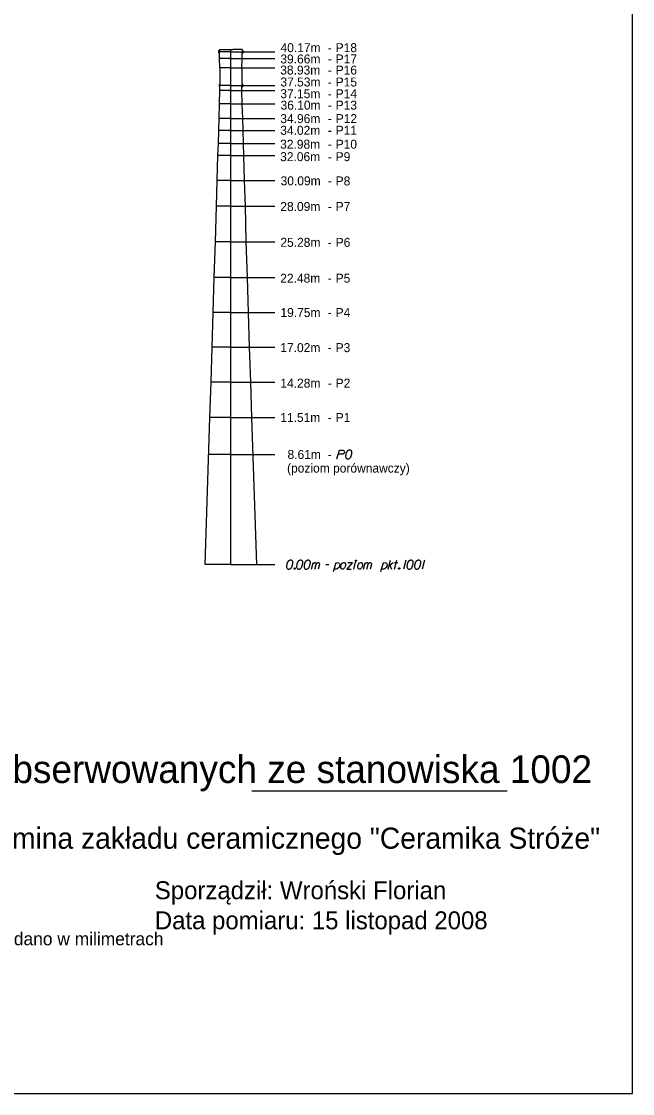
# Model space of a CAD drawing. Extents: x 138 to 6653, y -177 to 1520.
# Drawn here: x 387.51 to 398.01, y 2.29 to 20.71 of the extents above; entities that cross this region are included whole.
import ezdxf

# ---------------------------------------------------------------- set-up
doc = ezdxf.new("R2010")
doc.units = 0
doc.layers.add('Opisy', color=7, linetype='Continuous')
doc.layers.add('Ramka do drukowania', color=7, linetype='Continuous')

msp = doc.modelspace()

# ---------------------------------------------------------------- linework, layer by layer
at = {"layer": 'Opisy'}
for p, q in [((390.893, 20.204), (390.893, 20.185)), ((390.91, 20.204), (390.893, 20.204)), ((391.106, 20.185), (390.893, 20.185)), ((390.893, 20.185), (390.893, 20.166)), ((390.91, 20.166), (390.893, 20.166)), ((390.91, 20.222), (390.91, 20.204)), ((390.91, 20.222), (391.137, 20.222)), ((390.91, 20.072), (390.91, 20.166)), ((391.106, 11.376), (391.106, 20.222)), ((391.106, 20.185), (391.859, 20.185)), ((391.302, 20.222), (391.137, 20.222)), ((391.302, 20.222), (391.302, 20.204)), ((391.302, 20.204), (391.319, 20.204)), ((391.302, 20.166), (391.319, 20.166)), ((391.302, 20.072), (391.302, 20.166)), ((391.319, 20.204), (391.319, 20.185)), ((391.319, 20.185), (391.319, 20.166)), ((391.106, 20.072), (390.91, 20.072)), ((390.916, 19.912), (390.91, 20.072)), ((391.106, 19.912), (390.916, 19.912)), ((390.916, 19.912), (390.916, 19.624)), ((391.106, 20.072), (391.859, 20.072)), ((391.106, 19.912), (391.859, 19.912)), ((391.296, 19.912), (391.302, 20.072)), ((391.296, 19.912), (391.296, 19.624)), ((390.903, 19.624), (390.903, 19.605)), ((390.903, 19.624), (390.916, 19.624)), ((391.106, 19.605), (390.903, 19.605)), ((390.903, 19.605), (390.903, 19.586)), ((390.918, 19.586), (390.903, 19.586)), ((390.916, 19.522), (390.918, 19.586)), ((391.106, 19.605), (391.859, 19.605)), ((391.296, 19.522), (391.294, 19.586)), ((391.294, 19.586), (391.309, 19.586)), ((391.309, 19.624), (391.296, 19.624)), ((391.309, 19.624), (391.309, 19.605)), ((391.309, 19.605), (391.309, 19.586)), ((390.91, 19.291), (390.916, 19.522)), ((391.106, 19.522), (390.916, 19.522)), ((391.106, 19.522), (391.859, 19.522)), ((391.302, 19.291), (391.296, 19.522)), ((390.903, 19.041), (390.91, 19.291)), ((391.106, 19.291), (390.91, 19.291)), ((391.106, 19.291), (391.859, 19.291)), ((391.309, 19.041), (391.302, 19.291)), ((390.897, 18.835), (390.903, 19.041)), ((391.106, 19.041), (390.903, 19.041)), ((391.106, 19.041), (391.859, 19.041)), ((391.315, 18.835), (391.309, 19.041)), ((390.891, 18.607), (390.897, 18.835)), ((391.106, 18.835), (390.897, 18.835)), ((391.106, 18.835), (391.859, 18.835)), ((391.321, 18.607), (391.315, 18.835)), ((390.884, 18.405), (390.891, 18.607)), ((391.106, 18.607), (390.891, 18.607)), ((391.106, 18.607), (391.859, 18.607)), ((391.329, 18.405), (391.321, 18.607)), ((390.871, 17.973), (390.884, 18.405)), ((391.106, 18.405), (390.884, 18.405)), ((391.106, 18.405), (391.859, 18.405)), ((391.341, 17.973), (391.329, 18.405)), ((390.858, 17.535), (390.871, 17.973)), ((391.106, 17.973), (390.871, 17.973)), ((391.106, 17.973), (391.859, 17.973)), ((391.354, 17.535), (391.341, 17.973)), ((390.841, 16.918), (390.858, 17.535)), ((391.106, 17.535), (390.858, 17.535)), ((391.106, 17.535), (391.859, 17.535)), ((391.371, 16.918), (391.354, 17.535)), ((390.821, 16.305), (390.841, 16.918)), ((391.106, 16.918), (390.841, 16.918)), ((391.106, 16.918), (391.859, 16.918)), ((391.391, 16.305), (391.371, 16.918)), ((390.802, 15.706), (390.821, 16.305)), ((391.106, 16.305), (390.821, 16.305)), ((391.106, 16.305), (391.859, 16.305)), ((391.41, 15.706), (391.391, 16.305)), ((390.784, 15.108), (390.802, 15.706)), ((391.106, 15.706), (390.802, 15.706)), ((391.106, 15.706), (391.859, 15.706)), ((391.428, 15.108), (391.41, 15.706)), ((390.765, 14.506), (390.784, 15.108)), ((391.106, 15.108), (390.784, 15.108)), ((391.106, 15.108), (391.859, 15.108)), ((391.447, 14.506), (391.428, 15.108)), ((390.745, 13.9), (390.765, 14.506)), ((391.106, 14.506), (390.765, 14.506)), ((391.106, 14.506), (391.859, 14.506)), ((391.467, 13.9), (391.447, 14.506)), ((390.663, 11.376), (390.745, 13.9)), ((391.106, 13.9), (390.745, 13.9)), ((391.106, 13.9), (391.859, 13.9)), ((391.549, 11.376), (391.467, 13.9)), ((391.106, 13.263), (390.725, 13.263)), ((391.106, 13.263), (391.859, 13.263)), ((391.106, 11.376), (390.663, 11.376)), ((391.106, 11.376), (391.859, 11.376)), ((391.466, 7.488), (395.851, 7.488))]:
    msp.add_line(p, q, dxfattribs=at)
for points in [[(392.928, 13.189), (392.97, 13.343), (393.022, 13.343), (393.029, 13.342), (393.033, 13.34), (393.04, 13.337), (393.045, 13.333), (393.048, 13.328), (393.052, 13.322), (393.055, 13.314), (393.056, 13.306), (393.055, 13.3), (393.053, 13.295), (393.051, 13.291), (393.048, 13.287), (393.045, 13.282), (393.04, 13.278), (393.036, 13.276), (393.03, 13.274), (393.024, 13.272), (392.951, 13.272)], [(393.149, 13.343), (393.147, 13.343), (393.14, 13.342), (393.135, 13.34), (393.131, 13.339), (393.125, 13.337), (393.118, 13.333), (393.112, 13.329), (393.106, 13.325), (393.102, 13.32), (393.098, 13.314), (393.095, 13.308), (393.091, 13.3), (393.089, 13.295), (393.086, 13.288), (393.082, 13.276), (393.079, 13.258), (393.076, 13.243), (393.076, 13.23), (393.078, 13.22), (393.082, 13.209), (393.086, 13.203), (393.092, 13.196), (393.099, 13.191), (393.103, 13.19), (393.11, 13.189), (393.116, 13.189), (393.126, 13.19), (393.135, 13.192), (393.141, 13.196), (393.149, 13.202), (393.153, 13.206), (393.158, 13.21), (393.161, 13.215), (393.164, 13.219), (393.166, 13.225), (393.167, 13.227), (393.17, 13.234), (393.172, 13.241), (393.175, 13.248), (393.176, 13.253), (393.177, 13.257), (393.178, 13.261), (393.181, 13.272), (393.182, 13.278), (393.183, 13.285), (393.184, 13.293), (393.186, 13.304), (393.186, 13.308), (393.184, 13.312), (393.183, 13.317), (393.18, 13.325), (393.176, 13.329), (393.172, 13.333), (393.167, 13.337), (393.163, 13.339), (393.159, 13.34), (393.155, 13.342), (393.149, 13.343)], [(392.135, 11.45), (392.133, 11.45), (392.126, 11.449), (392.121, 11.448), (392.117, 11.447), (392.111, 11.444), (392.104, 11.441), (392.098, 11.437), (392.092, 11.432), (392.088, 11.427), (392.084, 11.421), (392.081, 11.415), (392.077, 11.408), (392.075, 11.403), (392.072, 11.396), (392.069, 11.384), (392.065, 11.365), (392.063, 11.351), (392.063, 11.337), (392.064, 11.328), (392.069, 11.317), (392.072, 11.311), (392.078, 11.303), (392.086, 11.299), (392.089, 11.297), (392.097, 11.296), (392.103, 11.296), (392.112, 11.297), (392.121, 11.3), (392.127, 11.303), (392.135, 11.31), (392.139, 11.313), (392.144, 11.318), (392.147, 11.323), (392.15, 11.327), (392.152, 11.333), (392.154, 11.335), (392.156, 11.341), (392.158, 11.348), (392.161, 11.356), (392.162, 11.361), (392.163, 11.364), (392.164, 11.369), (392.167, 11.38), (392.168, 11.386), (392.169, 11.392), (392.171, 11.401), (392.172, 11.412), (392.172, 11.415), (392.171, 11.42), (392.169, 11.425), (392.166, 11.432), (392.162, 11.437), (392.158, 11.441), (392.154, 11.444), (392.149, 11.447), (392.145, 11.448), (392.141, 11.449), (392.135, 11.45)], [(392.306, 11.45), (392.304, 11.45), (392.297, 11.449), (392.292, 11.448), (392.288, 11.447), (392.282, 11.444), (392.275, 11.441), (392.269, 11.437), (392.263, 11.432), (392.259, 11.427), (392.256, 11.421), (392.252, 11.415), (392.248, 11.408), (392.246, 11.403), (392.243, 11.396), (392.24, 11.384), (392.236, 11.365), (392.234, 11.351), (392.234, 11.337), (392.235, 11.328), (392.24, 11.317), (392.243, 11.311), (392.249, 11.303), (392.257, 11.299), (392.26, 11.297), (392.268, 11.296), (392.274, 11.296), (392.283, 11.297), (392.292, 11.3), (392.298, 11.303), (392.306, 11.31), (392.31, 11.313), (392.315, 11.318), (392.319, 11.323), (392.321, 11.327), (392.323, 11.333), (392.325, 11.335), (392.327, 11.341), (392.33, 11.348), (392.332, 11.356), (392.333, 11.361), (392.334, 11.364), (392.336, 11.369), (392.338, 11.38), (392.339, 11.386), (392.34, 11.392), (392.342, 11.401), (392.343, 11.412), (392.343, 11.415), (392.342, 11.42), (392.34, 11.425), (392.337, 11.432), (392.333, 11.437), (392.33, 11.441), (392.325, 11.444), (392.32, 11.447), (392.316, 11.448), (392.313, 11.449), (392.306, 11.45)], [(392.436, 11.45), (392.434, 11.45), (392.427, 11.449), (392.422, 11.448), (392.418, 11.447), (392.412, 11.444), (392.405, 11.441), (392.399, 11.437), (392.393, 11.432), (392.389, 11.427), (392.385, 11.421), (392.382, 11.415), (392.378, 11.408), (392.376, 11.403), (392.373, 11.396), (392.37, 11.384), (392.366, 11.365), (392.364, 11.351), (392.364, 11.337), (392.365, 11.328), (392.37, 11.317), (392.373, 11.311), (392.379, 11.303), (392.387, 11.299), (392.39, 11.297), (392.398, 11.296), (392.404, 11.296), (392.413, 11.297), (392.422, 11.3), (392.428, 11.303), (392.436, 11.31), (392.44, 11.313), (392.445, 11.318), (392.448, 11.323), (392.451, 11.327), (392.453, 11.333), (392.455, 11.335), (392.457, 11.341), (392.459, 11.348), (392.462, 11.356), (392.463, 11.361), (392.464, 11.364), (392.465, 11.369), (392.468, 11.38), (392.469, 11.386), (392.47, 11.392), (392.472, 11.401), (392.473, 11.412), (392.473, 11.415), (392.472, 11.42), (392.47, 11.425), (392.467, 11.432), (392.463, 11.437), (392.459, 11.441), (392.455, 11.444), (392.45, 11.447), (392.446, 11.448), (392.442, 11.449), (392.436, 11.45)], [(393.251, 11.45), (393.257, 11.45), (393.261, 11.448), (393.264, 11.443), (393.264, 11.437), (393.261, 11.432), (393.257, 11.43), (393.251, 11.43), (393.247, 11.432), (393.244, 11.437), (393.244, 11.443), (393.247, 11.448), (393.251, 11.45)], [(393.807, 11.296), (393.848, 11.45)], [(393.915, 11.296), (393.955, 11.45)], [(394.11, 11.45), (394.069, 11.296)], [(394.204, 11.45), (394.201, 11.45), (394.194, 11.449), (394.189, 11.448), (394.186, 11.447), (394.18, 11.444), (394.172, 11.441), (394.166, 11.437), (394.16, 11.432), (394.156, 11.427), (394.153, 11.421), (394.149, 11.415), (394.146, 11.408), (394.143, 11.403), (394.141, 11.396), (394.137, 11.384), (394.133, 11.365), (394.131, 11.351), (394.131, 11.337), (394.132, 11.328), (394.137, 11.317), (394.141, 11.311), (394.147, 11.303), (394.154, 11.299), (394.158, 11.297), (394.165, 11.296), (394.171, 11.296), (394.181, 11.297), (394.189, 11.3), (394.195, 11.303), (394.204, 11.31), (394.207, 11.313), (394.212, 11.318), (394.216, 11.323), (394.218, 11.327), (394.221, 11.333), (394.222, 11.335), (394.224, 11.341), (394.227, 11.348), (394.229, 11.356), (394.231, 11.361), (394.232, 11.364), (394.233, 11.369), (394.235, 11.38), (394.237, 11.386), (394.238, 11.392), (394.239, 11.401), (394.24, 11.412), (394.24, 11.415), (394.239, 11.42), (394.238, 11.425), (394.234, 11.432), (394.231, 11.437), (394.227, 11.441), (394.222, 11.444), (394.217, 11.447), (394.214, 11.448), (394.21, 11.449), (394.204, 11.45)], [(394.334, 11.45), (394.331, 11.45), (394.324, 11.449), (394.319, 11.448), (394.315, 11.447), (394.309, 11.444), (394.302, 11.441), (394.296, 11.437), (394.29, 11.432), (394.286, 11.427), (394.283, 11.421), (394.279, 11.415), (394.275, 11.408), (394.273, 11.403), (394.271, 11.396), (394.267, 11.384), (394.263, 11.365), (394.261, 11.351), (394.261, 11.337), (394.262, 11.328), (394.267, 11.317), (394.271, 11.311), (394.277, 11.303), (394.284, 11.299), (394.288, 11.297), (394.295, 11.296), (394.301, 11.296), (394.311, 11.297), (394.319, 11.3), (394.325, 11.303), (394.334, 11.31), (394.337, 11.313), (394.342, 11.318), (394.346, 11.323), (394.348, 11.327), (394.351, 11.333), (394.352, 11.335), (394.354, 11.341), (394.357, 11.348), (394.359, 11.356), (394.36, 11.361), (394.362, 11.364), (394.363, 11.369), (394.365, 11.38), (394.366, 11.386), (394.368, 11.392), (394.369, 11.401), (394.37, 11.412), (394.37, 11.415), (394.369, 11.42), (394.368, 11.425), (394.364, 11.432), (394.36, 11.437), (394.357, 11.441), (394.352, 11.444), (394.347, 11.447), (394.343, 11.448), (394.34, 11.449), (394.334, 11.45)], [(394.432, 11.45), (394.391, 11.296)], [(392.2, 11.317), (392.206, 11.317), (392.209, 11.314), (392.213, 11.31), (392.213, 11.303), (392.209, 11.299), (392.206, 11.296), (392.2, 11.296), (392.196, 11.299), (392.192, 11.303), (392.192, 11.31), (392.196, 11.314), (392.2, 11.317)], [(392.493, 11.296), (392.521, 11.407)], [(392.514, 11.378), (392.52, 11.391), (392.526, 11.398), (392.533, 11.403), (392.541, 11.407), (392.546, 11.409), (392.553, 11.409), (392.555, 11.408), (392.56, 11.403), (392.565, 11.397), (392.569, 11.386), (392.57, 11.38), (392.576, 11.391), (392.583, 11.398), (392.591, 11.403), (392.598, 11.407), (392.604, 11.409), (392.61, 11.409), (392.615, 11.408), (392.618, 11.403), (392.622, 11.397), (392.626, 11.386), (392.627, 11.38), (392.606, 11.296)], [(392.549, 11.296), (392.57, 11.38)], [(392.736, 11.374), (392.789, 11.374)], [(392.871, 11.256), (392.912, 11.408)], [(392.909, 11.395), (392.921, 11.404), (392.939, 11.408), (392.954, 11.405), (392.963, 11.398), (392.971, 11.388), (392.975, 11.375), (392.977, 11.363), (392.974, 11.352), (392.971, 11.339), (392.961, 11.324), (392.949, 11.311), (392.931, 11.299), (392.915, 11.296), (392.9, 11.297), (392.884, 11.306)], [(393.045, 11.408), (393.053, 11.408), (393.063, 11.403), (393.073, 11.39), (393.074, 11.384), (393.075, 11.378), (393.075, 11.373), (393.075, 11.354), (393.071, 11.342), (393.065, 11.328), (393.058, 11.316), (393.046, 11.305), (393.035, 11.296), (393.017, 11.296), (393.009, 11.299), (393.002, 11.305), (392.998, 11.311), (392.994, 11.325), (392.994, 11.347), (392.996, 11.354), (393.001, 11.37), (393.006, 11.379), (393.008, 11.384), (393.02, 11.397), (393.032, 11.404), (393.045, 11.408)], [(393.117, 11.41), (393.196, 11.41), (393.096, 11.296), (393.173, 11.296)], [(393.217, 11.296), (393.249, 11.414)], [(393.336, 11.408), (393.344, 11.408), (393.354, 11.403), (393.364, 11.39), (393.365, 11.384), (393.366, 11.378), (393.366, 11.373), (393.366, 11.354), (393.363, 11.342), (393.357, 11.328), (393.349, 11.316), (393.337, 11.305), (393.326, 11.296), (393.308, 11.296), (393.301, 11.299), (393.293, 11.305), (393.29, 11.311), (393.285, 11.325), (393.285, 11.347), (393.287, 11.354), (393.292, 11.37), (393.297, 11.379), (393.3, 11.384), (393.312, 11.397), (393.324, 11.404), (393.336, 11.408)], [(393.387, 11.296), (393.415, 11.407)], [(393.408, 11.378), (393.414, 11.391), (393.42, 11.398), (393.427, 11.403), (393.434, 11.407), (393.439, 11.409), (393.446, 11.409), (393.449, 11.408), (393.454, 11.403), (393.459, 11.397), (393.462, 11.386), (393.463, 11.38), (393.469, 11.391), (393.477, 11.398), (393.484, 11.403), (393.491, 11.407), (393.497, 11.409), (393.503, 11.409), (393.508, 11.408), (393.512, 11.403), (393.516, 11.397), (393.519, 11.386), (393.52, 11.38), (393.5, 11.296)], [(393.443, 11.296), (393.463, 11.38)], [(393.684, 11.256), (393.726, 11.408)], [(393.722, 11.395), (393.734, 11.404), (393.752, 11.408), (393.767, 11.405), (393.777, 11.398), (393.784, 11.388), (393.789, 11.375), (393.79, 11.363), (393.788, 11.352), (393.784, 11.339), (393.774, 11.324), (393.762, 11.311), (393.744, 11.299), (393.728, 11.296), (393.713, 11.297), (393.698, 11.306)], [(393.821, 11.351), (393.894, 11.412)], [(393.836, 11.363), (393.868, 11.296)], [(393.915, 11.408), (393.973, 11.408)], [(393.994, 11.317), (394, 11.317), (394.004, 11.314), (394.007, 11.31), (394.007, 11.303), (394.004, 11.299), (394, 11.296), (393.994, 11.296), (393.99, 11.299), (393.987, 11.303), (393.987, 11.31), (393.99, 11.314), (393.994, 11.317)]]:
    msp.add_lwpolyline(points, dxfattribs=at)
at = {"layer": 'Ramka do drukowania'}
for p, q in [((398.007, 2.285), (398.007, 31.985)), ((377.007, 2.285), (398.007, 2.285))]:
    msp.add_line(p, q, dxfattribs=at)

# ---------------------------------------------------------------- texts
at = {"layer": 'Opisy'}
for s, height, p in [('40.17m', 0.1542, (391.959, 20.179)), ('P18', 0.1542, (392.906, 20.179)), ('39.66m', 0.1542, (391.956, 19.985)), ('-', 0.154, (392.769, 20.179)), ('P17', 0.1542, (392.906, 19.985)), ('38.93m', 0.1542, (391.954, 19.794)), ('-', 0.154, (392.77, 19.985)), ('P16', 0.1542, (392.906, 19.794)), ('37.53m', 0.1542, (391.957, 19.589)), ('-', 0.154, (392.773, 19.794)), ('P15', 0.1542, (392.906, 19.589)), ('37.15m', 0.1542, (391.955, 19.388)), ('-', 0.154, (392.769, 19.589)), ('P14', 0.1542, (392.906, 19.388)), ('36.10m', 0.1542, (391.959, 19.191)), ('-', 0.154, (392.769, 19.388)), ('P13', 0.1542, (392.906, 19.191)), ('-', 0.154, (392.77, 19.191)), ('34.96m', 0.1542, (391.955, 18.96)), ('-', 0.154, (392.77, 18.96)), ('P12', 0.1542, (392.907, 18.96)), ('34.02m', 0.1542, (391.954, 18.759)), ('-', 0.154, (392.77, 18.759)), ('P11', 0.1542, (392.906, 18.759)), ('32.98m', 0.1542, (391.952, 18.52)), ('P10', 0.1542, (392.906, 18.52)), ('32.06m', 0.1542, (391.952, 18.306)), ('-', 0.154, (392.77, 18.52)), ('P9', 0.1542, (392.906, 18.306)), ('-', 0.154, (392.77, 18.306)), ('30.09m', 0.1542, (391.96, 17.891)), ('-', 0.154, (392.77, 17.891)), ('P8', 0.1542, (392.906, 17.889)), ('28.09m', 0.1542, (391.955, 17.45)), ('-', 0.154, (392.77, 17.45)), ('P7', 0.1542, (392.906, 17.45)), ('25.28m', 0.1542, (391.956, 16.834)), ('P6', 0.1542, (392.906, 16.834)), ('-', 0.154, (392.769, 16.834)), ('22.48m', 0.1542, (391.954, 16.218)), ('-', 0.154, (392.769, 16.218)), ('P5', 0.1542, (392.906, 16.218)), ('19.75m', 0.1542, (391.957, 15.628)), ('-', 0.154, (392.769, 15.628)), ('P4', 0.1542, (392.906, 15.628)), ('17.02m', 0.1542, (391.955, 15.025)), ('P3', 0.1542, (392.906, 15.025)), ('-', 0.154, (392.769, 15.025)), ('14.28m', 0.1542, (391.956, 14.415)), ('P2', 0.1542, (392.906, 14.415)), ('-', 0.154, (392.77, 14.415)), ('11.51m', 0.1542, (391.954, 13.825)), ('-', 0.154, (392.769, 13.825)), ('P1', 0.1542, (392.907, 13.825)), ('8.61m', 0.1542, (392.079, 13.189)), ('(poziom porównawczy)', 0.15416, (392.071, 12.955)), ('-', 0.154, (392.769, 13.189)), ('Wykres wychyleń osi komina obserwowanych ze stanowiska 1002', 0.47516, (378.7, 7.621)), ('Badanie pionowości i prostoliniowości komina zakładu ceramicznego "Ceramika Stróże"', 0.36281, (378.58, 6.492)), ('Sporządził: Wroński Florian', 0.30766, (389.799, 5.625)), ('Data pomiaru: 15 listopad 2008', 0.30766, (389.799, 5.108)), ('Wartości wychyleń komina dla poszczególnych poziomów podano w milimetrach', 0.22315, (379.333, 4.833))]:
    msp.add_text(s, height=height, dxfattribs=at).set_placement(p)

doc.saveas('drawing.dxf')
